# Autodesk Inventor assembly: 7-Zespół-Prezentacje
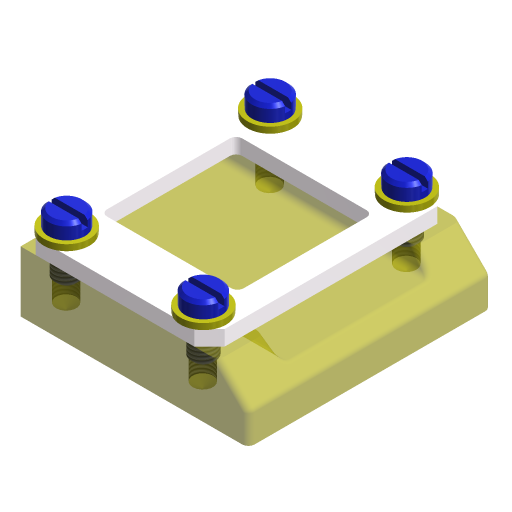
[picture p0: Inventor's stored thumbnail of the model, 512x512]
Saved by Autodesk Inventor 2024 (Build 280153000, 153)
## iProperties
Created: 2023-03
Part Number: 7-Zespół-Prezentacje
Document SubType Name: Assembly
Designer: Andrzej Jaskulski
Checked By: A.J.
Engr Approved By: Andrzej Jaskulski
Mfg Approved By: Andrzej Jaskulski
Authority: A.J.
Company: ATC
Control State: 0
Master: False
Checked Out: False
Shininess: 20.0
Length Units: 11269
Angle Units: 11279
Time Units: 11290
Mass Units: 11283
Length Display Precision: 3
Angle Display Precision: 2
Compacted: True
Density: 0.0
Volumn: 0.0
Area: 0.0
PropertySet Name: Model Information
Title: A.J.: Kurs R2024-MEP
Author: Andrzej Jaskulski
Revision Number: 1/24
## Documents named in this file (5)
- C:\Users\AndJas\Documents\R2024-MEP\Obszar roboczy\7-Zespół-Prezentacje.iam
- C:\Users\AndJas\Documents\R2024-MEP\Obszar roboczy\PG.ipt
- C:\Users\AndJas\Documents\R2024-MEP\Obszar roboczy\P.ipt
- C:\Users\AndJas\Documents\R2024-MEP\Obszar roboczy\POD.ipt
- C:\Users\AndJas\Documents\R2024-MEP\Obszar roboczy\W.ipt
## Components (10 placed, 4 different names)
1. Płyta — Zestawiające:1, Zestawiające:2
2. PG:1 — Zestawiające:1, Zestawiające:2, Wstawiające:1, Wstawiające:2, Wstawiające:3, Wstawiające:4
3. POD:1 — Wstawiające:1, Wstawiające:7
4. W:1 — Wstawiające:7
5. POD:2 — Wstawiające:2, Wstawiające:8
6. W:2 — Wstawiające:8
7. POD:3 — Wstawiające:3, Wstawiające:5
8. W:3 — Wstawiające:5
9. POD:4 — Wstawiające:4, Wstawiające:6
10. W:4 — Wstawiające:6
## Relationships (10: Insert 8, Mate 2)
- Zestawiające:1 [Mate]: Płyta ↔ PG:1
- Zestawiające:2 [Mate]: Płyta ↔ PG:1
- Wstawiające:1 [Insert]: PG:1 ↔ POD:1
- Wstawiające:2 [Insert]: PG:1 ↔ POD:2
- Wstawiające:3 [Insert]: PG:1 ↔ POD:3
- Wstawiające:4 [Insert]: PG:1 ↔ POD:4
- Wstawiające:5 [Insert]: POD:3 ↔ W:3
- Wstawiające:6 [Insert]: POD:4 ↔ W:4
- Wstawiające:7 [Insert]: POD:1 ↔ W:1
- Wstawiające:8 [Insert]: POD:2 ↔ W:2
